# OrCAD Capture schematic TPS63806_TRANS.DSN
size D; title: TPS63806 2-A, high-efficient, low IQ buck-boost converter with; rev: 1.0; note: Datasheet: SLVSDS9B  EVM: NA; note: Synchronous Step Down Converter; note: small solution size
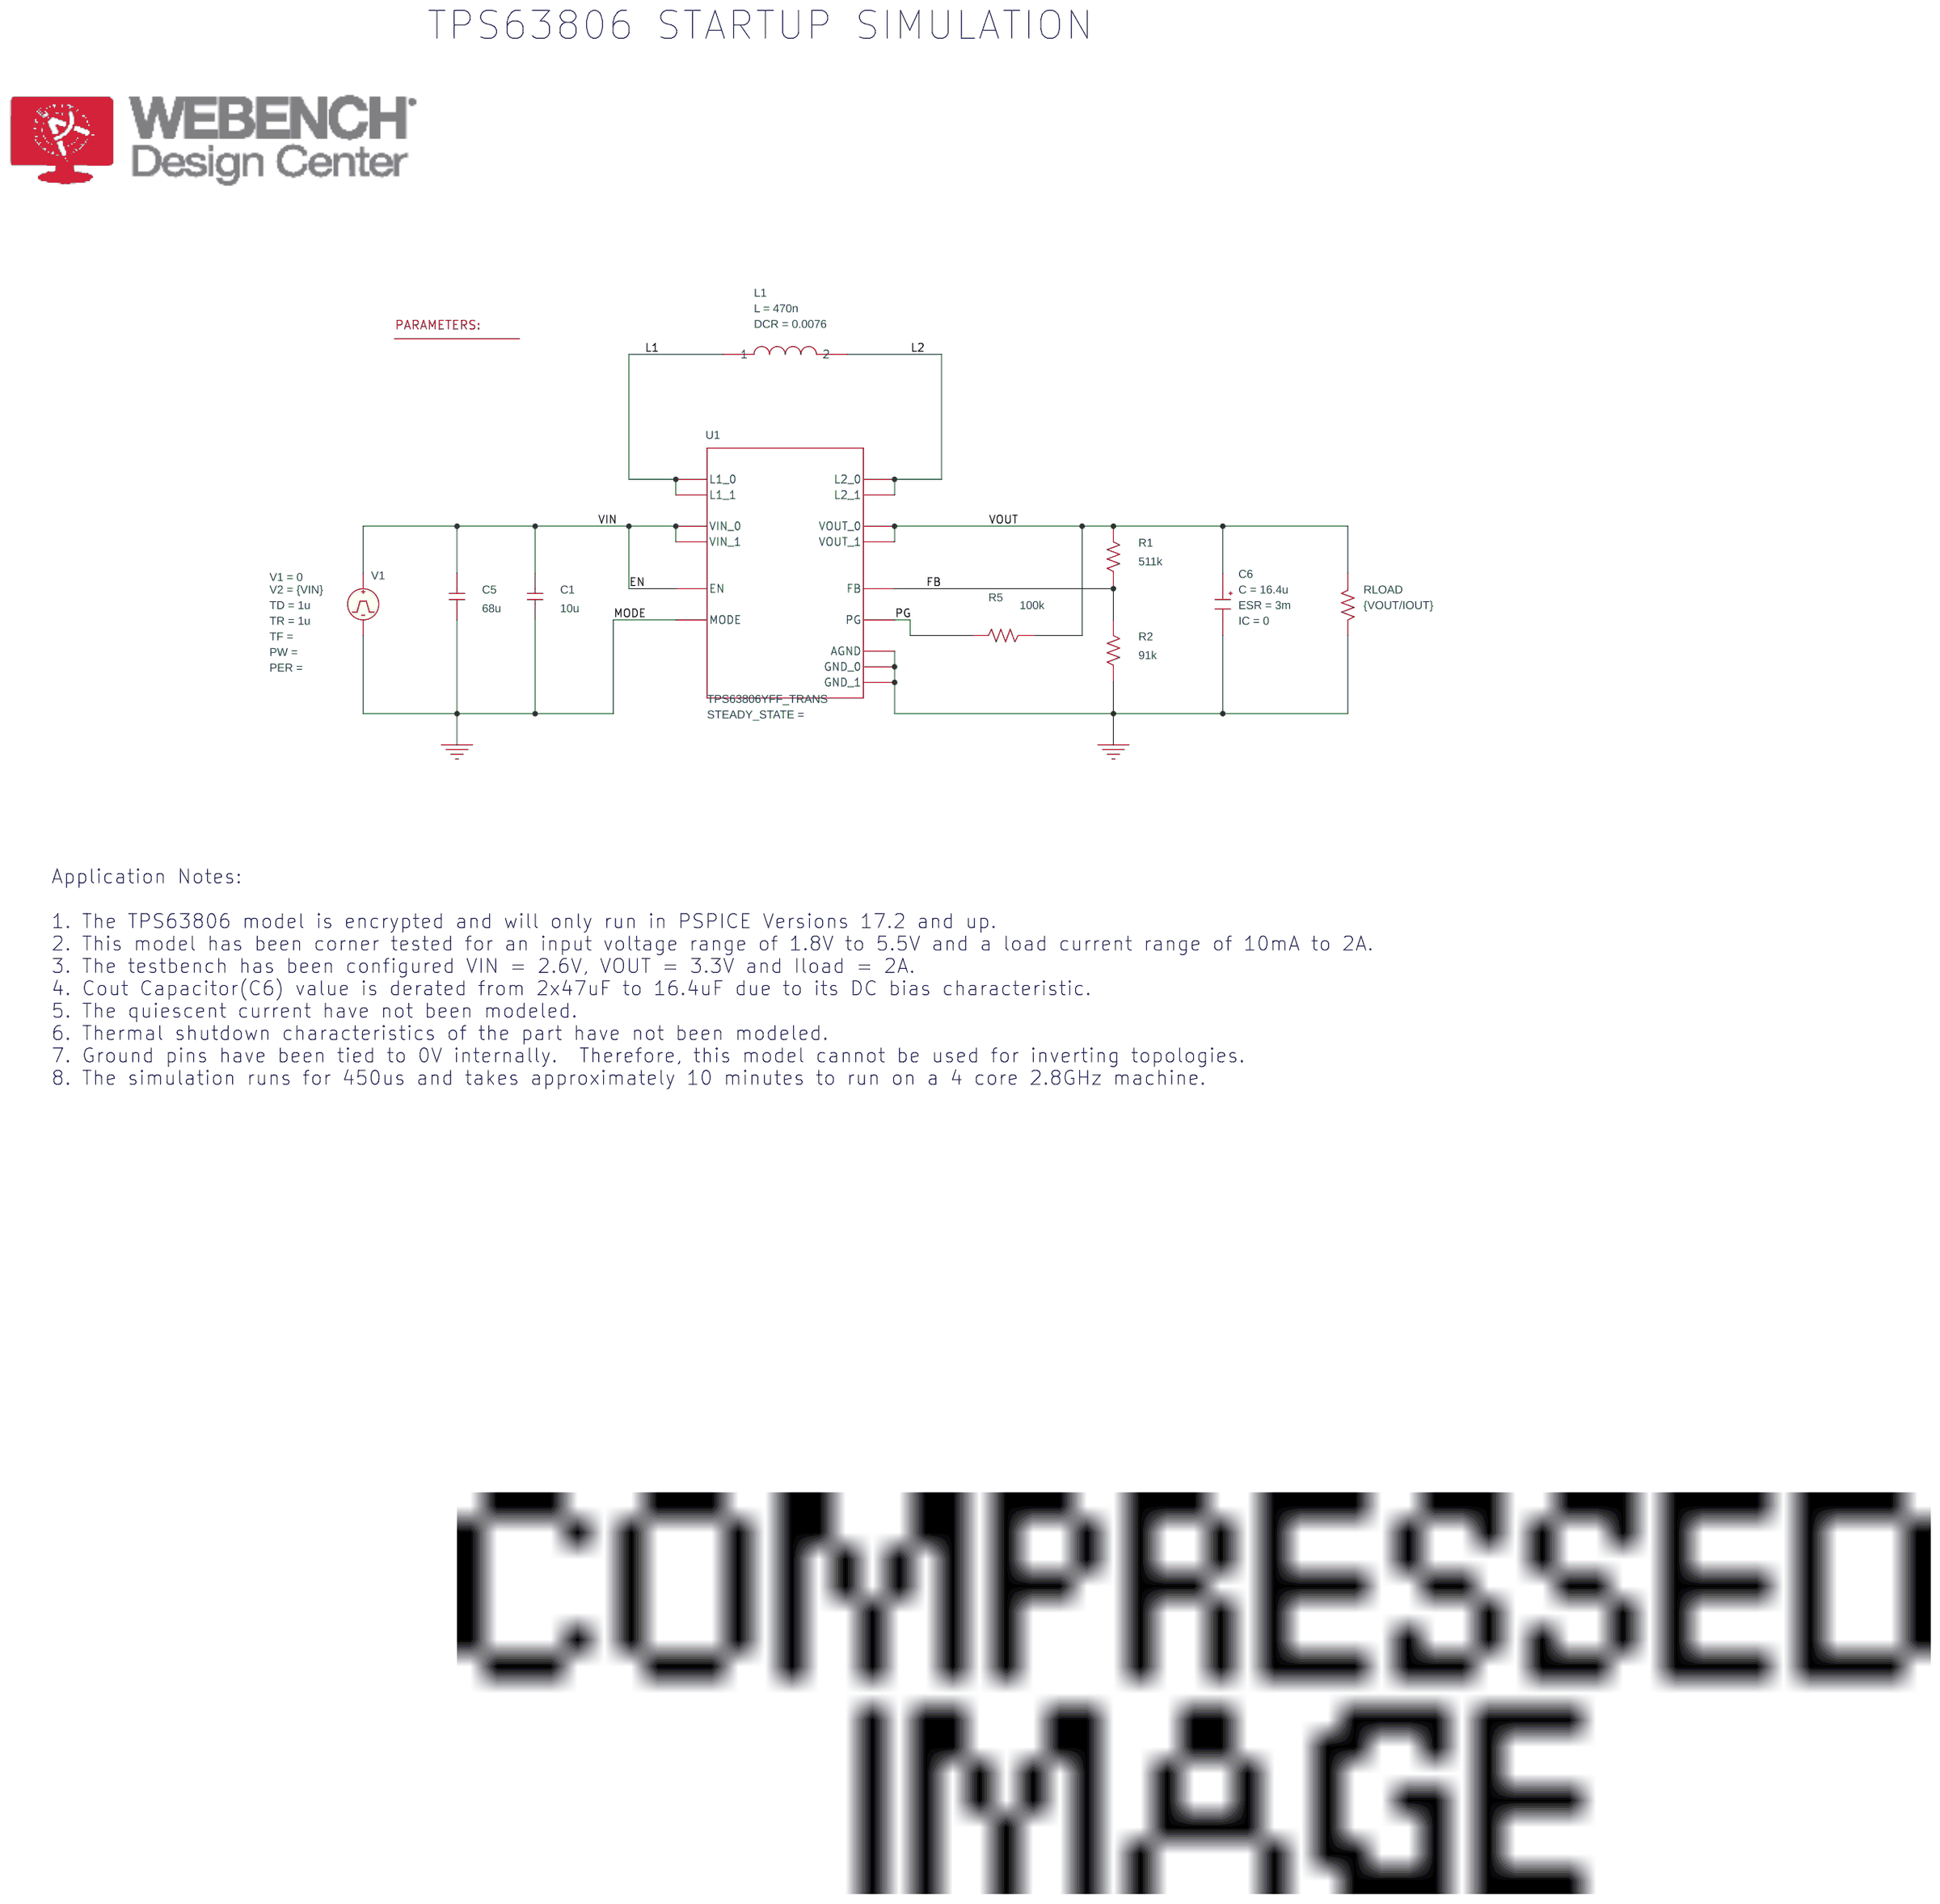
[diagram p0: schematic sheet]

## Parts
1  PARAM
C1  10u  [RAD/CK05]
C5  68u  [RAD/CK05]
C6  CESR
L1  LDCR
R1  511k  [AX/RC05]
R2  91k  [AX/RC05]
R5  100k  [AX/RC05]
RLOAD  {VOUT/IOUT}  [AX/RC05]
U1  TPS63806YFF_TRANS  [YFF0015]
V1  VPULSE

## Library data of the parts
1 = PARAM: IOUT: 2; VIN: 2.6; VOUT: 3.3
C1 C5 = C
C6 = CESR_0: C: 16.4u; ESR: 3m; IC: 0; PSpiceTemplate: X^@REFDES %IN %OUT @MODEL PARAMS:  ?C|C=@C||C=100u|  ?ESR|ESR=@ESR||ESR=0.01| ?X|X=@X||X=2|  ?IC|IC=@IC||IC=2|; X: 1
L1 = LDCR: DCR: 0.0076; L: 470n
R1 R2 R5 RLOAD = R
U1 = TPS63806YFF_TRANS: < Value >: TPS63806YFF; PartNumber: TPS63806YFF
V1 = VPULSE: TD: 1u; TR: 1u; V1: 0; V2: {VIN}

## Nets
0: C1.2 C5.2 C6.2(OUT) R2.1 RLOAD.2 U1.AGND U1.GND_0 U1.GND_1 U1.MODE V1.2(-)
EN: C1.1 C5.1 U1.EN U1.VIN_0 U1.VIN_1 V1.1(+)
FB: R1.1 R2.2 U1.FB
L1: L1.1 U1.L1_0 U1.L1_1
L2: L1.2 U1.L2_0 U1.L2_1
PG: R5.2 U1.PG
VOUT: C6.1(IN) R1.2 R5.1 RLOAD.1 U1.VOUT_0 U1.VOUT_1

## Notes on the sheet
- TPS63806 STARTUP SIMULATION
- Application Notes:
  1. The TPS63806 model is encrypted and will only run in PSPICE Versions 17.2 and up.
  2. This model has been corner tested for an input voltage range of 1.8V to 5.5V and a load current range of 10mA to 2A.
  3. The testbench has been configured VIN = 2.6V, VOUT = 3.3V and Iload = 2A.
  4. Cout Capacitor(C6) value is derated from 2x47uF to 16.4uF due to its DC bias characteristic.
  5. The quiescent current have not been modeled.
  6. Thermal shutdown characteristics of the part have not been modeled.
  7. Ground pins have been tied to 0V internally.  Therefore, this model cannot be used for inverting topologies.
  8. The simulation runs for 450us and takes approximately 10 minutes to run on a 4 core 2.8GHz machine.
